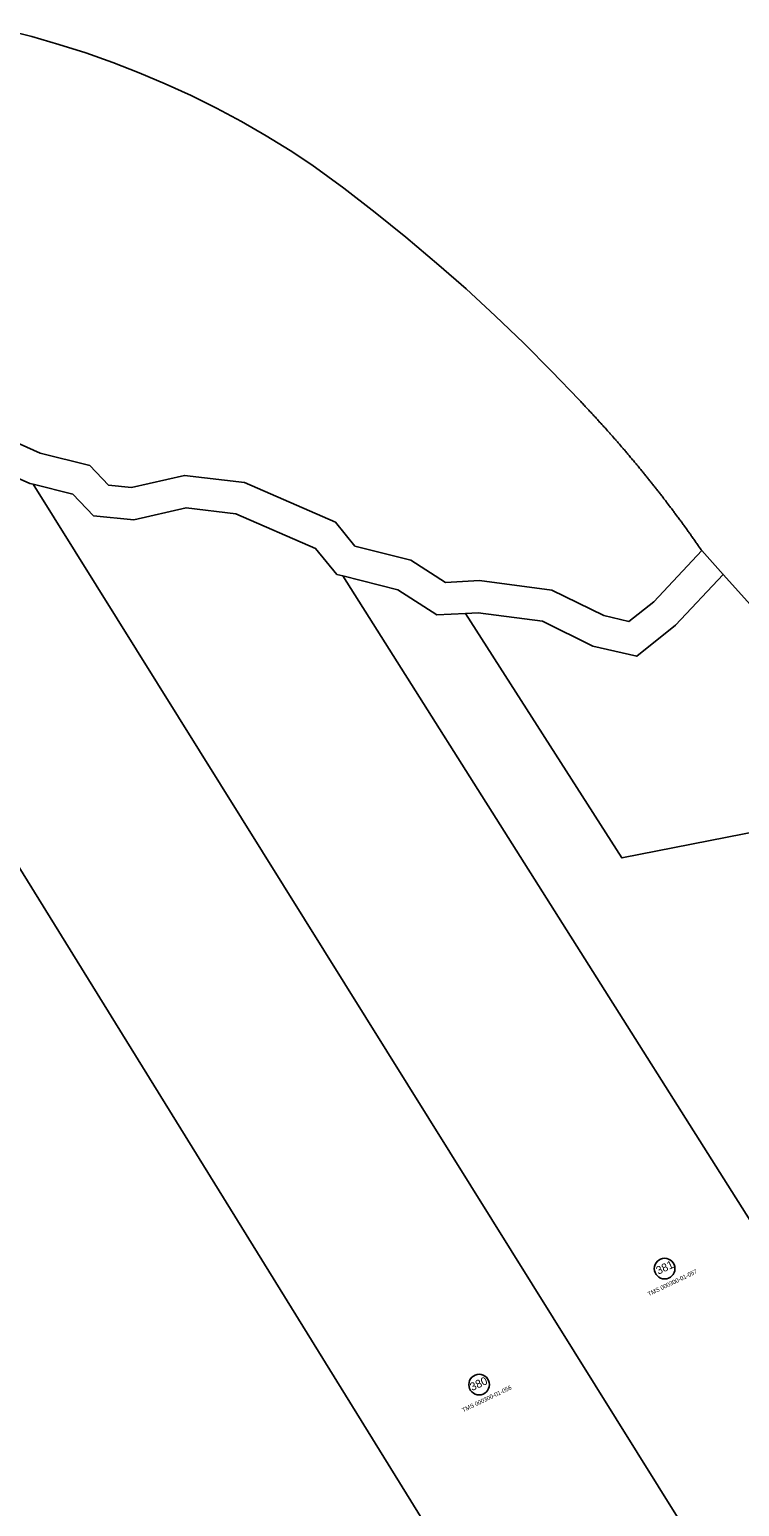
# Model space of a CAD drawing. Extents: x 1854757 to 1948870, y 823643 to 877716.
# Drawn here: x 1902616 to 1903282, y 853837 to 855221 of the extents above; entities that cross this region are included whole.
import ezdxf

# ---------------------------------------------------------------- set-up
doc = ezdxf.new("R2010")
doc.units = 0
for name, color, linetype in [('Butler baseline', 7, 'Continuous'), ('Flatiron trailer_2', 7, 'Continuous'), ('RD_EX_H2O_WetLd', 7, 'Continuous')]:
    doc.layers.add(name, color=color, linetype=linetype)

msp = doc.modelspace()

# ---------------------------------------------------------------- linework, layer by layer
at = {"layer": 'Butler baseline'}
for centre in [(1903211.6, 854059.7), (1903037.7, 853951)]:
    msp.add_circle(centre, 9.65, dxfattribs=at)
at = {"layer": 'RD_EX_H2O_WetLd'}
for points in [[(1902592.4, 855220.8), (1902618.2, 855214.2), (1902643.8, 855206.9), (1902669.1, 855198.8), (1902694.2, 855189.9), (1902718.9, 855180.3), (1902743.4, 855170), (1902767.6, 855158.9), (1902791.4, 855147.1), (1902814.9, 855134.6), (1902838, 855121.3), (1902860.6, 855107.4), (1902881, 855094.1), (1902910.9, 855072.1), (1902940.3, 855049.4), (1902969.1, 855026.1), (1903000, 855000), (1903025.4, 854977.7), (1903052.7, 854952.6), (1903079.5, 854926.9), (1903105.7, 854900.6), (1903131.4, 854873.8), (1903132.3, 854872.8), (1903133, 854872.1), (1903133.7, 854871.4), (1903134.4, 854870.6), (1903135.1, 854869.9), (1903135.7, 854869.2), (1903136.4, 854868.4), (1903137.1, 854867.7), (1903137.8, 854867), (1903138.5, 854866.3), (1903139.2, 854865.5), (1903139.9, 854864.8), (1903140.5, 854864.1), (1903141.2, 854863.3), (1903141.9, 854862.6), (1903142.6, 854861.9), (1903143.3, 854861.1), (1903143.9, 854860.4), (1903144.6, 854859.7), (1903145.3, 854858.9), (1903146, 854858.2), (1903146.7, 854857.5), (1903147.3, 854856.7), (1903148, 854856), (1903148.7, 854855.3), (1903149.4, 854854.5), (1903150, 854853.8), (1903150.7, 854853), (1903151.4, 854852.3), (1903152.1, 854851.6), (1903152.7, 854850.8), (1903153.4, 854850.1), (1903154.1, 854849.3), (1903154.7, 854848.6), (1903155.4, 854847.9), (1903156.1, 854847.1), (1903156.7, 854846.4), (1903157.4, 854845.6), (1903158.1, 854844.9), (1903158.7, 854844.1), (1903159.4, 854843.4), (1903160.1, 854842.6), (1903160.7, 854841.9), (1903161.4, 854841.1), (1903162.1, 854840.4), (1903162.7, 854839.6), (1903163.4, 854838.9), (1903164, 854838.1), (1903164.7, 854837.4), (1903165.4, 854836.6), (1903166, 854835.9), (1903166.7, 854835.1), (1903167.3, 854834.4), (1903168, 854833.6), (1903168.6, 854832.9), (1903169.3, 854832.1), (1903170, 854831.4), (1903170.6, 854830.6), (1903171.3, 854829.8), (1903171.9, 854829.1), (1903172.6, 854828.3), (1903173.2, 854827.6), (1903173.9, 854826.8), (1903174.5, 854826), (1903175.2, 854825.3), (1903175.8, 854824.5), (1903176.5, 854823.8), (1903177.1, 854823), (1903177.8, 854822.2), (1903178.4, 854821.5), (1903179, 854820.7), (1903179.7, 854819.9), (1903180.3, 854819.2), (1903181, 854818.4), (1903181.6, 854817.6), (1903182.3, 854816.9), (1903182.9, 854816.1), (1903183.5, 854815.3), (1903184.2, 854814.6), (1903184.8, 854813.8), (1903185.5, 854813), (1903186.1, 854812.3), (1903186.7, 854811.5), (1903187.4, 854810.7), (1903188, 854809.9), (1903188.6, 854809.2), (1903189.3, 854808.4), (1903189.9, 854807.6), (1903190.5, 854806.9), (1903191.2, 854806.1), (1903191.8, 854805.3), (1903192.4, 854804.5), (1903193.1, 854803.8), (1903193.7, 854803), (1903194.3, 854802.2), (1903195, 854801.4), (1903195.6, 854800.6), (1903196.2, 854799.9), (1903196.8, 854799.1), (1903197.5, 854798.3), (1903198.1, 854797.5), (1903198.7, 854796.7), (1903199.3, 854796), (1903200, 854795.2), (1903200.6, 854794.4), (1903201.2, 854793.6), (1903201.8, 854792.8), (1903202.4, 854792), (1903203.1, 854791.3), (1903203.7, 854790.5), (1903204.3, 854789.7), (1903204.9, 854788.9), (1903205.5, 854788.1), (1903206.1, 854787.3), (1903206.8, 854786.5), (1903207.4, 854785.7), (1903208, 854785), (1903208.6, 854784.2), (1903209.2, 854783.4), (1903209.8, 854782.6), (1903210.4, 854781.8), (1903211, 854781), (1903211.7, 854780.2), (1903212.3, 854779.4), (1903212.9, 854778.6), (1903213.5, 854777.8), (1903214.1, 854777), (1903214.7, 854776.2), (1903215.3, 854775.4), (1903215.9, 854774.6), (1903216.5, 854773.8), (1903217.1, 854773), (1903217.7, 854772.2), (1903218.3, 854771.5), (1903218.9, 854770.7), (1903219.5, 854769.9), (1903220.1, 854769.1), (1903220.7, 854768.3), (1903221.3, 854767.5), (1903221.9, 854766.7), (1903222.5, 854765.8), (1903223.1, 854765), (1903223.7, 854764.2), (1903224.3, 854763.4), (1903224.9, 854762.6), (1903225.5, 854761.8), (1903226.1, 854761), (1903226.7, 854760.2), (1903227.3, 854759.4), (1903227.9, 854758.6), (1903228.4, 854757.8), (1903229, 854757), (1903229.6, 854756.2), (1903230.2, 854755.4), (1903230.8, 854754.6), (1903231.4, 854753.8), (1903232, 854752.9), (1903232.6, 854752.1), (1903233.1, 854751.3), (1903233.7, 854750.5), (1903234.3, 854749.7), (1903234.9, 854748.9), (1903235.5, 854748.1), (1903236.1, 854747.3), (1903236.6, 854746.4), (1903237.2, 854745.6), (1903237.8, 854744.8), (1903238.4, 854744), (1903238.9, 854743.2), (1903239.5, 854742.4), (1903240.1, 854741.5), (1903240.7, 854740.7), (1903241.2, 854739.9), (1903241.8, 854739.1), (1903242.4, 854738.3), (1903243, 854737.4), (1903243.5, 854736.6), (1903244.1, 854735.8), (1903244.7, 854735), (1903245.2, 854734.2), (1903245.8, 854733.3), (1903246.4, 854732.5), (1903201.5, 854684.6), (1903178.2, 854666.1), (1903154.5, 854671.6), (1903105.9, 854695.4), (1903037.9, 854704.4), (1903006.2, 854702.7), (1902973.6, 854723.6), (1902921.2, 854736.8), (1902902.9, 854759.3), (1902817.6, 854796.2), (1902761.4, 854803), (1902711.9, 854791.7), (1902690.3, 854793.8), (1902672.7, 854812.3), (1902626.3, 854823.9), (1902579.2, 854844.7)], [(1903159.9, 853541.1), (1902423.6, 854730.7), (1902434, 854755.6), (1902436.3, 854755.5), (1902471.4, 854741.4), (1902505.9, 854772.2), (1902536, 854787.9), (1902556.3, 854813.4), (1902563, 854818.7), (1902568.1, 854816.8), (1902616.5, 854795.5), (1902619.7, 854794.7), (1903322.1, 853669.1)], [(1902619.7, 854794.7), (1902656.9, 854785.3), (1902676.3, 854765), (1902713.9, 854761.4), (1902763, 854772.6), (1902809.6, 854767), (1902884.3, 854734.6), (1902904.3, 854710.2), (1902909.8, 854708.8)], [(1903246.4, 854732.5), (1903266.6, 854710.2)], [(1903494.1, 853784.8), (1902909.8, 854708.8), (1902961.5, 854695.7), (1902998.2, 854672.2), (1903024.8, 854673.7), (1903171.5, 854444.6), (1903302.2, 854470.2)], [(1903024.8, 854673.7), (1903036.7, 854674.3), (1903097.1, 854666.3), (1903144.4, 854643.1), (1903185.5, 854633.5), (1903221.9, 854662.5), (1903266.6, 854710.2), (1903349.1, 854618.7)]]:
    msp.add_lwpolyline(points, dxfattribs=at)

# ---------------------------------------------------------------- texts
at = {"layer": 'Butler baseline'}
for s, p in [('381', (1903205.7, 854053.9)), ('380', (1903031.2, 853944.9))]:
    msp.add_text(s, height=7.5, rotation=24.8809, dxfattribs=at).set_placement(p)
at = {"layer": 'Flatiron trailer_2'}
for s, p in [('TMS 000300-01-057', (1903196.9, 854033.8)), ('TMS 000300-01-056', (1903022.9, 853925))]:
    msp.add_text(s, height=4, rotation=25.6077, dxfattribs=at).set_placement(p)

doc.saveas('drawing.dxf')
